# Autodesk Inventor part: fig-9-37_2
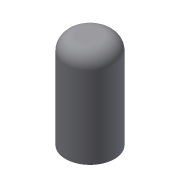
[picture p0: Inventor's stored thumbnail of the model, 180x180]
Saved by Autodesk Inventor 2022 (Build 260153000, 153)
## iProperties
Created: 2013-03
Part Number: fig-9-37_2
Material: Generic
Document SubType Name: Modeling
Designer: CADCIM
Density: 1 g/cm^3
Appearance: Default
Author: CADCIM
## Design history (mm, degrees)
sketch "Sketch1"
  geometry: C1 r 9 at (0, 0); 1 further point
  constraints: 1 centre point, 1 coincident
  dimensions: "d0" = 18 diameter of C1
extrude "Extrusion1" new body sketch "Sketch1" distance "d2" = 35; taper "d3" = 0 deg
fillet "Fillet1" dims "d4" = 5
body "Solid1"
